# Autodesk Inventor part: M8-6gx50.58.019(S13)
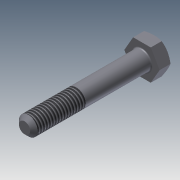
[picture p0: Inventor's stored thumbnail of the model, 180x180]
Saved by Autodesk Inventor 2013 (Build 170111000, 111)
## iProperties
Shininess: 20.0
Length Units: 11269
Angle Units: 11279
Time Units: 11290
Mass Units: 11283
Length Display Precision: 3
Angle Display Precision: 2
Created: 2001-07
Part Number: M8-6gx50.58.019(S13)
Material: Steel, Mild
Document SubType Name: Modeling
Designer: TEvgeniy
Density: 7.86 g/cm^3
Density: 0.0
Volumn: 0.0
Area: 0.0
PropertySet Name: Model Information
Control State: 0
Master: False
Checked Out: False
Checked Out Date: 2008-10-15
Last Check In Date: 2008-10-15
Author: TEvgeniy
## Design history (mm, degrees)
sketch "Sketch1"
  geometry: L1 (482.08, 469.325)-(474.575, 469.325); L2 (485.833, 462.825)-(482.08, 469.325); L3 (482.08, 456.325)-(485.833, 462.825); L4 (474.575, 456.325)-(482.08, 456.325); L5 (470.822, 462.825)-(474.575, 456.325); L6 (474.575, 469.325)-(470.822, 462.825); C1 r 6.5 at (478.327, 462.825)
  constraints: 12 end point, 6 tangent, 3 parallel, 1 centre point, 1 horizontal, 1 other
  dimensions: "d1" = 120 deg angle of L1 L2; "d3" = 120 deg angle of L5 L6; "d5" = 13 diameter of C1
extrude "ExtrusionBlind1" new body sketch "Sketch1" distance "d6" = 5.3; taper "d7" = 0 deg
sketch "Sketch2"
  geometry: C1 r 6.4 at (478.327, -462.825)
  constraints: 1 centre point
  dimensions: "d12" = 12.8 diameter of C1
extrude "ExtrusionThru1" sketch "Sketch2" stored distance "d13" = 0.13; taper "d14" = 60 deg
sketch "Sketch3"
  geometry: L1 (470.822, 462.825)-(471.322, 463.691); L2 (474.575, 469.325)-(475.575, 469.325); L3 (482.08, 469.325)-(482.58, 468.459); C1 r 4 at (478.327, 462.825); C2 r 6.5 at (478.327, 462.825)
  constraints: 6 end point, 3 tangent, 2 centre point, 1 coincident
  dimensions: "d16" = 8 diameter of C1
extrude "ExtrusionBlind2" join sketch "Sketch3" distance "d17" = 50; taper "d18" = 0 deg
fillet "Fillet1" dims "d19" = 0.5
feature "Резьба1" dims "d23" = 22, "d24" = 0
chamfer "Фаска2" distance "d25" = 1.6; stored, may be unused: second distance "d26" = 2, angle "d27" = 45 deg
body "Solid1"
other parameters: "d0" = 120 deg (derived), "d2" = 120 deg (derived), "d4" = 13 (derived), "d8" = 0, "d9" = 0, "d10" = 0, "d11" = 12.8 (derived), "d15" = 8 (derived)
